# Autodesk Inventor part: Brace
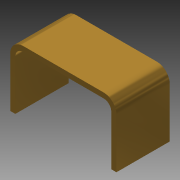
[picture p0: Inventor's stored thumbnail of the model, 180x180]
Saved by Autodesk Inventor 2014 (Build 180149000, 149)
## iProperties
Shininess: 64.0
Length Units: 11269
Angle Units: 11279
Time Units: 11290
Mass Units: 11283
Length Display Precision: 3
Angle Display Precision: 2
Created: 2002-08
Part Number: Brace
Document SubType Name: Sheet Metal
Designer: t_munrn
Density: 1 g/cm^3
Sheet Metal Rule: Default
Material: Generic
Appearance: Brass - Satin
Density: 0.0
Volumn: 0.0
Area: 0.0
PropertySet Name: Model Information
Control State: 0
Master: False
Checked Out: False
Author: t_munrn
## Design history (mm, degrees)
node "Contour Flange1"
  sketch "Sketch1"
    geometry: L1 (-112.5, -135)-(-112.5, 0); L2 (-112.5, 0)-(112.5, 0); L3 (112.5, 0)-(112.5, -135); 2 further points
    constraints: 6 end point, 2 parallel, 1 coincident, 1 midpoint, 1 perpendicular, 1 vertical
    dimensions: "d0" = 225 distance of L1.end L2.end; "d1" = 135 distance of L1.start L1.end
body "Solid1"
face "Plate1" dims "d2" = 125, "d4" = 18 (= BendRadius), "d5" = 12, "Thickness" = 12, "MinimumRemnant" = 24 (= 2 x Thickness), "BendReliefWidth" = 12 (= Thickness)
bend "Bend1" dims "d4" = 18 (= BendRadius), "d5" = 12, "d6" = 12 (= BendReliefWidth), "d7" = 6 (= BendReliefDepth), "d8" = 24 (= MinimumRemnant), "SeamGap" = 0.01, "Thickness" = 12, "MinimumRemnant" = 24 (= 2 x Thickness), "BendReliefWidth" = 12 (= Thickness), "TransitionRadius" = 18 (= BendRadius)
other parameters: "BendRadius" = 18 (= 1.5 x Thickness), "BendReliefDepth" = 6 (= 0.5 x Thickness), "CornerReliefSize" = 48 (= 4 x Thickness), "d3" = 18 (= BendRadius), "JacobiRadiusSize" = 12 (= Thickness), "GapSize" = 12 (= Thickness)
